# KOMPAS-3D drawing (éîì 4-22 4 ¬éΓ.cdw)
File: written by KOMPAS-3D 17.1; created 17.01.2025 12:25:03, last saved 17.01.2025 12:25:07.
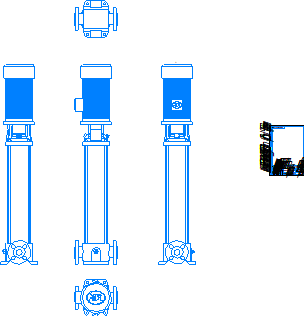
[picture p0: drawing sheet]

Sheet 1: A4, portrait

Title block, sheet 1: name: ВМН 4-22 4 кВт; designation: ВМН 4-22 4 кВт; material: Сталь 10  ГОСТ 1050-2013; mass: 54,2; sheets: 1; sheet format: A4; stored path: \\adlc.lan\data\АДЛ_ПКД\3D-модели\ADL production\Насосы ГРАНПАМП\Насосы ВМН\ВМН4\KOMPAS 3D\ВМН 4-22 4 кВт.cdw

Views: Вид 1, Спереди, Проекционный вид 2, Проекционный вид 3, Проекционный вид 4, Проекционный вид 5
Referenced files in \\adlc.lan\data\АДЛ_ПКД\3D-модели\ADL production\Насосы ГРАНПАМП\Насосы ВМН\ВМН4\KOMPAS 3D\: ВМН 4-22 4 кВт.m3d
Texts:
  Andrey
  АДЛ
Dimensions and other numbers on the sheet: 1:1; 1; 54,2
